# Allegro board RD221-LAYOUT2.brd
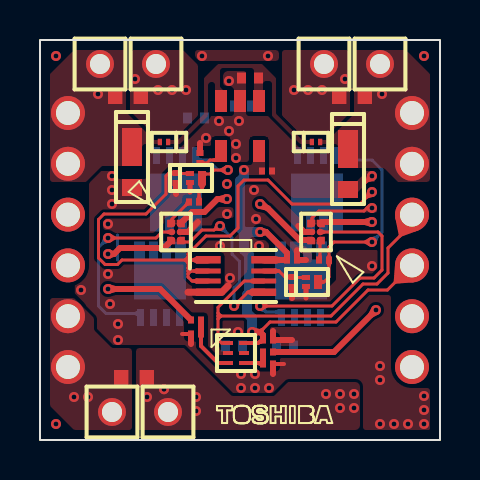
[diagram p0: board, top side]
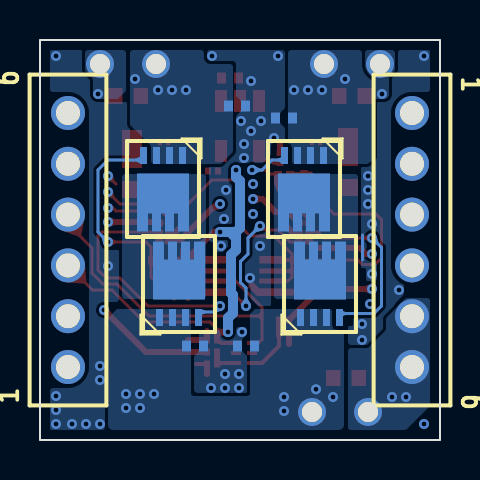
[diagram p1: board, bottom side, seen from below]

Outline 20 x 20 mm; copper layers: TOP, CONDUCTIVE2, CONDUCTIVE3, BOTTOM. Coordinates in mm from the lower left corner of the outline.
Outline path: rectangle 0,0 20,20

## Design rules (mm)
constraint set DEFAULT: 

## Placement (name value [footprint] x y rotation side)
C201  -  [KC00051KD]  10.5 18.1 180 top
C202  -  [KC00540KD]  8 14.1 90 top
C203  -  [KC00540KD]  11.35 13.45 0 top
C204  -  [KC00051KD]  7.8 16.1 0 bottom
C205  -  [KC00051KD]  9.7 4.7 0 bottom
C206  -  [KC00540KD]  11.4 5 0 top
C207  -  [KC00051KD]  10.15 16.7 180 bottom
C208  -  [KC00051KD]  12.25 4.7 180 bottom
C209  -  [KC00540KD]  12.6 9 0 top
CN201  -  [CU12000TD]  1.4 16.35 270 bottom
CN202  -  [CU12000TD]  18.6 3.65 90 bottom
D201  -  [MM02020KD]  4.6 13.9 90 top
D202  -  [MM02020KD]  15.4 13.8 90 top
D203  -  [KC10480CD]  6.2 14.9 0 top
D204  -  [KC10480CD]  13.8 14.9 180 top
DP201  -  [DP002X0KD]  3 18.8 0 top
DP202  -  [DP002X0KD]  5.8 18.8 0 top
DP203  -  [DP002X0KD]  17 18.8 0 top
DP204  -  [DP002X0KD]  14.2 18.8 0 top
DP205  -  [DP002X0KD]  6.4 1.4 0 top
DP206  -  [DP002X0KD]  3.6 1.4 0 top
IC201  -  [MM00631KD]  10 15.7 180 top
IC202  -  [DIC8T60KD]  9.8 8.2 270 top
IC203  -  [LA10251KD]  9.8 4.35 270 top
IC204  -  [BA10620KD]  6.8 10.4 270 top
IC205  -  [BA10620KD]  13.8 10.4 90 top
JP201  -  [KC00081KD]  4.4 17.2 0 top
JP202  -  [KC00081KD]  15.6 17.2 180 top
JP203  -  [KC00081KD]  4.7 3.1 180 top
NOREF  -  []  8 0 0 top
Q201  -  [LA10710KD]  7.8 13.1 0 top
Q202  -  [LA10710KD]  13.6 7.9 0 top
Q203  -  [SN00611KD]  6.8 12.55 0 bottom
Q204  -  [SN00611KD]  6 7.8 180 bottom
Q205  -  [SN00611KD]  13.85 12.55 0 bottom
Q206  -  [SN00611KD]  13.05 7.8 180 bottom
R201  -  [KC00540KD]  7.8 6 0 top
R202  -  [KC00540KD]  7.8 5.3 180 top
R203  -  [KC00540KD]  11.4 4.4 180 top
R204  -  [KC00540KD]  11.4 3.8 0 top
R205  -  [KC00540KD]  7.7 11.9 180 top
R206  -  [KC00540KD]  14.2 9 180 top
R207  -  [KC00540KD]  6.8 13.1 270 top
R208  -  [KC00540KD]  12.6 7.9 270 top

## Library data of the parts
C201 C204 C205 C207 C208 = DP0000016125
C202 = DP0010383000
C203 = DP0007093000
C206 C209 = DP0000015403
CN201 CN202 = DP0010563000
D201 = DP0010580000
D202 = DP0010558000
D203 D204 = DP0010560000
DP201-DP206 = DP9000817000
IC201 = DP0008120000
IC202 = DP0001429000
IC203 = DP0010561000
IC204 = DP0010579000
IC205 = DP0010556000
JP201-JP203 = DP0001376000
Q201 Q202 = DP0010513000
Q203-Q206 = DP0010582000
R201 = DP0000151160
R202 = DP0000151148
R203 R204 = DP0000152120
R205 R206 = DP0000155124
R207 R208 = DP0002867000

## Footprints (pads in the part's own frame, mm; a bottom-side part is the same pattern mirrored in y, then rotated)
BA10620KD
  round 0.325 smd: A1(-0.4,-0.2) A2(-0.4,0.2) B1(0,-0.2) B2(0,0.2) C1(0.4,-0.2) C2(0.4,0.2)
CU12000TD
  round 1.7 hole 1.2: 1(0,0) 2(2.54,0) 3(5.08,0) 4(7.62,0) 5(10.16,0) 6(12.7,0)
DIC8T60KD
  rect 0.375x1.24 smd: 1(-0.812,-1.385) 4(0.812,-1.385) 5(0.812,1.385) 8(-0.812,1.385)
  rect 0.25x1.24 smd: 2(-0.25,-1.385) 3(0.25,-1.385) 6(0.25,1.385) 7(-0.25,1.385)
DP002X0KD
  round 1.397 hole 1: 1(0,0)
KC00051KD
  rect 0.45x0.55 smd: 1(-0.425,0) 2(0.425,0)
KC00081KD
  rect 0.72x0.8 smd: 1(-0.64,0) 2(0.64,0)
KC00540KD
  rect 0.3x0.35 smd: 1(-0.25,0) 2(0.25,0)
KC10480CD
  rect 0.21x0.32 smd: A(-0.205,0) C(0.205,0)
LA10251KD
  rect 0.2x0.5 smd: 1(-0.5,-0.4) 2(0,-0.4) 3(0.5,-0.4) 4(0.5,0.4) 5(0,0.4) 6(-0.5,0.4)
LA10710KD
  rect 0.4x0.7 smd: D(0.3,0)
  rect 0.4x0.25 smd: G(-0.3,0.225) S(-0.3,-0.225)
MM00631KD
  rect 0.6x1.1 smd: 1(-0.95,-1.25) 2(0,-1.25) 3(0.95,-1.25) 4(0.95,1.25) 5(-0.95,1.25)
MM02020KD
  rect 0.85x1 smd: A(-1.275,0)
  rect 1.9x1 smd: C(0.75,0)
SN00611KD
  rect 0.35x0.85 smd: 1(-0.975,-1.675) 2(-0.325,-1.675) 3(0.325,-1.675) 4(0.975,-1.675)
  custom 0.65x0.65 smd: 5(0,0.675)

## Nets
GND: C201.2 C202.2 C203.2 C204.2 C205.2 C206.2 C207.2 C208.2 C209.2 CN201.3 CN201.4 D201.A D202.A IC201.2 IC202.4 IC203.2 IC204.B2 IC205.B2 Q201.S Q202.S R202.2 R204.2 R207.2 R208.2
VINA: CN201.1 CN201.2 D201.C D203.A DP201.1 JP201.1 R201.1
VINB: CN202.5 CN202.6 D202.C D204.A DP203.1 JP202.1 R203.1
EN20V: CN202.1 IC202.1 IC202.2 IC202.3 Q201.G R207.1
FLAG: CN202.4 IC202.6 IC203.1
LDO-VOUT: C203.1 C206.1 C209.1 CN202.3 IC201.5 IC202.8 IC203.6
SIG190: IC204.A1 R205.2
SIG191: IC205.B1 Q206.4
SIG192: IC205.A1 R206.2
SIG193: C207.1 DP204.1 IC205.A2 JP202.2 Q205.1 Q205.2 Q205.3
SIG195: C201.1 D203.C D204.C IC201.1 IC201.3
SIG196: IC203.4 R203.2 R204.1
SIG203: C205.1 C208.1 DP205.1 IC204.C1 IC205.C1 JP203.1 Q204.1 Q204.2 Q204.3 Q206.1 Q206.2 Q206.3
SIG204: IC202.7 Q202.G R208.1
SIG205: C204.1 DP202.1 IC204.A2 JP201.2 Q203.1 Q203.2 Q203.3
SIG206: Q201.D Q203.4 R205.1
SIG207: Q203.5 Q204.5
SIG208: IC204.B1 Q204.4
SIG209: IC202.5 IC204.C2
SIG210: Q205.5 Q206.5
SIG211: Q202.D Q205.4 R206.1
SIG213: IC203.3 R201.2 R202.1
SIG214: C202.1 IC201.4
VCT5V: CN202.2 IC205.C2
VOUT: CN201.5 CN201.6 DP206.1 JP203.2

Pads without a net: IC203 5

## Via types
v1: diameter 0.5, hole 0.25, TOP to BOTTOM, 82 vias

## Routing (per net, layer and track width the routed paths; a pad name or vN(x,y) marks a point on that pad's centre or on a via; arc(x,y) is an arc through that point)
GND: length 21.4
  TOP w0.15: v1(16.6,13.2) 16.2,12.8
  TOP w0.2: 12.2,3.8 R204.2 ; R202.2 7.1,5.3
  TOP w0.25: Q202.S 13.3,7.1 ; Q201.S 7.5,12.4
  TOP w0.3: 12.85,9.49 C209.2 13.3,9 ; R202.2 7.55,4.8 ; R207.2 6.8,12.3 ; R208.2 12.6,7.1 ; IC205.B2 13.22,10.4 12.92,10.7 ; 12.6,5 C206.2 11.65,5.45 ; R204.2 11.65,3.3 ; IC204.B2 7.4,10.4 7.9,10.9 ; C202.2 8,14.85
  TOP w0.35: 7.4,7.39 IC202.4 9.09,7.39 9.41,7.71
  CONDUCTIVE2 w0.15: 6.15,0.57 6.67,0.57 ; 3.35,0.57 3.9,0.57
  CONDUCTIVE2 w1: 1.4,12.45 CN201.3 ; CN201.3 CN201.4 ; CN201.3 2.5,11.27 ; CN201.4 1.4,7.55 ; CN201.4 2.4,8.73
  CONDUCTIVE3 w0.15: 6.17,0.57 6.62,0.57
  BOTTOM w0.15: 3.88,10.25 3.88,9
  vias: v1(0.8,19.2) v1(0.8,0.8) v1(2.05,7.5) v1(3.4,10.8) v1(3.4,8.3) v1(3.5,6.8) v1(3.6,13.2) v1(3.6,12.5) v1(3.6,11.8) v1(3.9,5.8) v1(3.9,5) v1(8.1,19.2) v1(8.3,15.1) v1(8.95,15.95) v1(9,9.7) v1(9.35,12.8) v1(9.35,11.3) v1(9.45,17.95) v1(9.45,15.45) v1(9.5,8.1) v1(9.8,14.8) v1(9.8,14.1) v1(9.95,15.95) v1(9.9,5.4) v1(10.05,3.3) v1(10.05,2.6) v1(10.7,12.5) v1(10.8,11.05) v1(10.75,3.3) v1(10.75,2.6) v1(10.95,9.7) v1(11.4,19.2) v1(11.45,2.6) v1(16.6,8.7) v1(17,3.7) v1(17,3) v1(17,0.8) v1(17.7,0.8) v1(18.4,0.8) v1(19.2,19.2) v1(19.2,2.2) v1(19.2,1.5) v1(19.2,0.8)
VINA: length 15.2
  TOP w0.3: v1(3.4,7.55) 6,7.55 R201.1
  CONDUCTIVE3 w0.6: v1(3.4,7.55) 3.05,7.55 2.65,7.95 2.65,17.05 v1(2.9,17.3)
VINB: length 17.2
  TOP w0.3: v1(16.8,6.5) 14.7,4.4 R203.1
  CONDUCTIVE3 w0.6: v1(17.1,17.3) 17.35,16.79 17.35,6.85 17,6.5 v1(16.8,6.5)
EN20V: length 41.1
  TOP w0.15: 7.4,8.85 7.4,9 ; 7.4,8.85 7.25,9 ; 7.4,8.85 7.4,8.6 ; 7.4,8.85 7.55,9 ; 7.4,9 7.25,9 ; 7.4,9 7.55,9 ; 7.4,9 7.4,9.15 ; 7.4,8.45 7.4,8.6 ; 7.4,8.45 7.4,8.3 ; 7.4,8.45 7.55,8.45 ; 7.4,8.6 7.55,8.45 ; 7.25,9 7.4,9.15 ; 7.25,9 4.1,9 3.88,8.78 3.25,8.78 2.92,9.1 2.92,11.03 3.2,11.3 5.3,11.3 6.3,12.3 6.3,13.2 6.45,13.35 R207.1 7.1,13.32 7.42,13.32 ; 7.4,9.15 7.4,9.3 8.3,10.2 9.5,10.2 9.9,10.6 9.9,12.7 10.2,13 11.4,13 12.6,11.8 16,11.8 v1(16.6,12.4) ; 7.4,9.15 7.55,9 ; 7.55,8.45 7.83,8.45 ; 7.55,8.45 7.4,8.3 ; 7.55,9 7.87,9 ; 7.4,8.3 7.4,8.15 7.6,7.95 7.83,7.95
  TOP w0.25: IC202.3 7.83,7.95 ; Q201.G 7.42,13.32 ; 7.83,8.45 IC202.2
  TOP w0.35: 7.87,9 8.4,9
  CONDUCTIVE2 w0.15: v1(16.6,12.4) 16.05,11.85 16.05,10.8 16.5,10.35 16.8,10.35 17.25,9.9 17.25,5 CN202.1
FLAG: length 18.2
  TOP w0.15: CN202.4 18,10.2 17.4,9.6 17.4,8.35 16.85,7.8 16.15,7.8 14.55,6.2 9.05,6.2 ; 8.9,6.2 8.9,6.35 ; 8.9,6.2 8.9,6.05 ; 8.9,6.2 9.05,6.2 ; 8.9,6.35 9.05,6.2 ; 8.9,6.35 8.9,6.63 10.22,7.95 10.69,7.95 ; 9.05,6.2 8.9,6.05 ; 9.25,4.85 9.07,4.85 8.9,5.03 8.9,6.05
  TOP w0.2: 9.25,4.85 IC203.1
  TOP w0.25: IC202.6 10.69,7.95
LDO-VOUT: length 23.9
  TOP w0.15: CN202.3 17.37,7.5 16.4,7.5 14.8,5.9 11.5,5.9 11,5.4
  TOP w0.2: C206.1 10.9,4.85 IC203.6
  TOP w0.3: v1(10.6,5.4) 11,5.4 11.15,5.25 C206.1 ; 11.79,9 C209.1 12.35,9.36 11.31,10.4 v1(11,10.4)
  TOP w0.35: 11.79,9 11.19,9
  BOTTOM w0.5: 10.2,10.1 10.2,10.4 ; 10.2,10.1 10.2,9.5 10.45,9.25 10.45,7.35 10.35,7.25 10.35,6.35 10.6,6.1 v1(10.6,5.4) ; 10.2,10.1 10.5,10.4 ; 10.2,10.4 10,10.6 10,12.95 10.2,13.15 v1(10.2,13.5) ; 10.2,10.4 10.5,10.4 ; 10.5,10.4 v1(11,10.4)
SIG190: length 1.5
  TOP w0.15: IC204.A1 6.6,11.05 R205.2
SIG191: length 12.9
  TOP w0.15: v1(11,6.7) 14.6,6.7 16,8.1 16.7,8.1 17.1,8.5 17.1,10.2 16.9,10.4 IC205.B1
  BOTTOM w0.15: 11.98,6.4 11.3,6.4 v1(11,6.7)
  BOTTOM w0.3: 11.98,6.4 12.07,6.4
SIG192: length 1
  TOP w0.15: R206.2 14,9.2 IC205.A1
SIG193: length 9.9
  TOP w0.3: v1(11,11.8) 11.4,11.58 12.98,10 IC205.A2
  CONDUCTIVE3 w0.6: v1(12.7,17.5) 11.9,16.7 11.9,12.4 11.3,11.8 v1(11,11.8)
  vias: v1(13.4,17.5) v1(14.1,17.5) v1(15.25,18.05)
SIG196: length 1.6
  TOP w0.2: R204.1 10.9,3.85 IC203.4
  TOP w0.3: R203.2 R204.1
SIG203: length 28.1
  TOP w0.3: v1(3.4,9.3) 3.7,9.3 4,9.6 6.2,9.6 IC204.C1 ; IC205.C1 14.1,10.9 v1(16.6,10.9)
  CONDUCTIVE3 w0.5: v1(3.4,9.3) 5.15,9.3 5.35,9.1 ; 5.35,9.1 5.35,8.35 ; 5.35,9.1 5.55,8.9 5.9,8.9 ; 5.35,8.35 v1(5.35,2.15) ; 5.35,8.35 5.9,8.9 ; 5.9,8.9 11.3,8.9 13.3,10.9 v1(16.6,10.9)
  vias: v1(6.2,2.54) v1(7.8,2.15) v1(7.8,1.45) v1(14.3,2.3) v1(15,2.3) v1(15,1.6) v1(15.7,2.3) v1(15.7,1.6)
SIG204: length 2.2
  TOP w0.15: 13.22,8.12 12.9,8.12 R208.1 12.25,8.15 11.95,8.45 11.77,8.45
  TOP w0.25: Q202.G 13.22,8.12 ; 11.77,8.45 IC202.7
SIG205: length 9.6
  TOP w0.3: v1(9.35,12.05) 8.87,12.05 8.22,11.4 7.6,11.4 IC204.A2
  CONDUCTIVE3 w0.6: v1(7.3,17.5) 7.3,13.4 8.65,12.05 v1(9.35,12.05)
  vias: v1(4.75,18.05) v1(5.9,17.5) v1(6.6,17.5)
SIG206: length 4.5
  TOP w0.15: 8.1,12.84 8.1,12.5 7.95,12.35 7.95,11.99 ; 8.1,13.3 8.5,13.3 8.7,13.5 v1(9.4,13.5)
  TOP w0.3: R205.1 7.95,11.99
  TOP w0.4: 8.1,12.84 Q201.D
  BOTTOM w0.15: 7.87,14 8.4,14 8.9,13.5 v1(9.4,13.5)
  BOTTOM w0.3: 7.87,14 7.78,14
SIG208: length 9.2
  TOP w0.15: v1(3.4,10.1) 5.8,10.1 6.1,10.4 IC204.B1
  BOTTOM w0.15: 4.95,6.33 3.3,6.33 2.92,6.7 2.92,9.62 v1(3.4,10.1)
  BOTTOM w0.3: 5.05,6.33 4.95,6.33
SIG209: length 8.6
  TOP w0.15: v1(9,10.7) 8.7,10.5 8.1,10.5 7.5,9.9 7.25,9.9 IC204.C2 ; v1(9.7,6.7) 10.39,7.39 10.65,7.39
  TOP w0.37: 10.65,7.39 IC202.5
  BOTTOM w0.15: v1(9,10.7) 9.6,10.1 9.6,9.3 9.97,8.93 9.97,7.88 9.7,7.6 v1(9.7,6.7)
SIG211: length 10.7
  TOP w0.15: 14.45,8.9 14.45,8.15 14.2,7.9 Q202.D ; v1(16.6,9.9) 14.7,9.9 14.45,9.65 14.45,9.02
  TOP w0.3: 14.45,8.9 R206.1 14.45,9.02
  BOTTOM w0.15: v1(16.6,9.9) 17.1,10.4 17.1,13.5 16.6,14 14.93,14
  BOTTOM w0.35: 14.82,14 14.93,14
SIG213: length 3
  TOP w0.2: IC203.3 8.9,3.85 8.05,4.7 R202.1
  TOP w0.3: R202.1 R201.2
SIG214: length 1.1
  TOP w0.15: 8.02,13.85 8.35,13.85 8.5,14 8.77,14
  TOP w0.2: 8.77,14 9,14
  TOP w0.3: C202.1 8.02,13.85
VCT5V: length 9.7
  TOP w0.15: IC205.C2 13.6,11.1 13.95,11.45 16.2,11.45 16.35,11.6 v1(16.6,11.6)
  CONDUCTIVE2 w0.15: CN202.2 17.65,7.14 17.65,10.55 v1(16.6,11.6)
VOUT:
  vias: v1(1.7,2.15) v1(2.4,2.15)

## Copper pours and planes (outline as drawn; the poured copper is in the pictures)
GND on TOP: 9.28,5.15 9.17,5.19 9.12,5.3 9.12,5.9 9.15,5.95 9.2,5.97 10.12,5.97 10.18,5.95 10.2,5.9 10.2,5.3 10.16,5.19 10.05,5.15
GND on TOP: 3.79,10.35 3.77,10.35 3.75,10.36 3.5,10.49 3.4,10.5 3.3,10.5 3.19,10.54 3.15,10.65 3.15,10.9 3.16,10.93 3.17,10.95 3.27,11.05 3.3,11.07 3.32,11.07 5.3,11.07 5.39,11.09 5.46,11.14 6.46,12.14 6.52,12.24 6.53,12.3 6.53,12.35 6.57,12.46 6.67,12.5 7.55,12.5 7.6,12.48 7.62,12.43 7.62,12.35 7.6,12.3 7.55,12.28 7.33,12.28 7.17,12.21 7.1,12.05 7.1,11.9 7.09,11.87 7.08,11.85 6.44,11.21 6.4,11.17 6.38,11.16 6.26,11.08 6.21,10.94 6.21,10.91 6.2,10.89 6.19,10.86 5.7,10.37 5.67,10.36 5.64,10.35
GND on TOP: 8.02,18.95 7.92,18.99 7.79,19.12 7.75,19.22 7.75,19.35 7.79,19.46 7.9,19.5 11.8,19.5 11.91,19.46 11.95,19.35 11.95,19.1 11.91,18.99 11.8,18.95
GND on TOP: outline of 88 points within 7.93,7.4 13.6,12.78
GND on TOP: 12.53,6.92 12.47,6.95 12.45,7 12.45,7.22 12.47,7.28 12.53,7.3 14.04,7.3 14.1,7.31 14.14,7.34 14.76,7.96 14.79,8 14.8,8.06 14.8,9.27 14.81,9.3 14.82,9.32 14.98,9.48 15,9.49 15.03,9.5 16.8,9.5 16.85,9.48 16.88,9.43 16.88,8.62 16.87,8.6 16.85,8.57 16.63,8.35 16.6,8.33 16.58,8.32 16,8.32 15.91,8.31 15.84,8.26 14.53,6.95 14.5,6.93 14.48,6.92
GND on TOP: outline of 298 points within 1.74,0.5 19.5,18.45
GND on BOTTOM: outline of 105 points within 0.5,4.75 4.6,19.5
GND on BOTTOM: 16.9,0.5 16.79,0.54 16.75,0.65 16.75,6.03 16.77,6.08 16.82,6.1 17.2,6.51 16.8,6.9 16.2,6.9 16.09,6.94 16.05,7.05 16.05,9.43 16.07,9.48 16.12,9.5 16.6,9.5 16.84,9.58 16.99,9.79 17.04,10.01 17.06,10.05 17.26,10.24 17.31,10.31 17.32,10.4 17.32,13.5 17.31,13.59 17.26,13.66 16.76,14.16 16.69,14.21 16.6,14.22 15.57,14.22 15.52,14.25 15.5,14.3 15.5,15.51 15.51,15.54 15.52,15.56 15.56,15.6 15.63,15.7 15.65,15.81 15.65,16.82 15.67,16.88 15.72,16.9 17.1,16.9 17.38,17.02 17.5,17.3 17.5,17.96 17.51,17.99 17.52,18.01 17.81,18.3 17.86,18.35 17.88,18.42 17.9,18.46 17.9,18.51 17.9,19.35 17.89,19.41 17.91,19.47 17.97,19.5 19.43,19.5 19.48,19.48 19.5,19.43 19.5,17.55 19.46,17.44 19.35,17.4 18.6,17.4 17.86,17.09 17.55,16.35 17.55,3.65 17.86,2.91 18.6,2.6 19.35,2.6 19.46,2.56 19.5,2.45 19.5,0.57 19.48,0.52 19.43,0.5
GND on BOTTOM: outline of 95 points within 7.75,9.4 11.65,19.5 ; 1 cut-out
GND on CONDUCTIVE2: outline of 155 points within 0.5,0.5 19.5,19.5 ; 22 cut-outs
GND on CONDUCTIVE3: outline of 101 points within 0.5,9.3 19.5,19.5 ; 7 cut-outs
GND on CONDUCTIVE3: outline of 115 points within 0.5,0.5 19.5,10.5 ; 6 cut-outs
VINA on BOTTOM: 2.8,17.05 2.62,17.12 2.55,17.3 2.55,18.09 2.51,18.19 2.29,18.41 2.25,18.51 2.25,19.35 2.29,19.46 2.4,19.5 3.6,19.5 3.7,19.47 3.75,19.38 3.75,19.35 3.75,18.8 3.67,18.46 3.44,18.2 3.34,18.12 3.27,18.04 3.25,17.94 3.25,17.12 3.23,17.07 3.17,17.05
VINB on TOP: 17.92,12.9 17.88,12.91 17.86,12.94 17.24,13.56 17.14,13.6 15.05,13.6 14.94,13.64 14.9,13.75 14.9,14.65 14.86,14.76 14.75,14.8 13.97,14.8 13.92,14.82 13.9,14.88 13.9,14.93 13.92,14.98 13.97,15 14.28,15 14.39,15.02 14.49,15.09 15.66,16.26 15.69,16.3 15.7,16.36 15.7,19.35 15.74,19.46 15.85,19.5 18.24,19.5 18.3,19.49 18.34,19.46 19.46,18.34 19.49,18.3 19.5,18.24 19.5,13.05 19.46,12.94 19.35,12.9
VINB on BOTTOM: 16.16,17.05 16.06,17.09 15.74,17.41 15.7,17.51 15.7,19.35 15.74,19.46 15.85,19.5 17.6,19.5 17.71,19.46 17.75,19.35 17.75,18.51 17.71,18.41 17.39,18.09 17.35,17.99 17.35,17.3 17.32,17.18 17.23,17.08 17.1,17.05
LDO-VOUT on TOP: 10.1,13.25 9.99,13.29 9.95,13.4 9.95,13.6 9.99,13.71 10.1,13.75 10.49,13.75 10.55,13.76 10.59,13.79 10.61,13.81 10.65,13.91 10.65,14.75 10.69,14.86 10.8,14.9 11.1,14.9 11.21,14.86 11.25,14.75 11.25,13.4 11.21,13.29 11.1,13.25
SIG193 on TOP: 13.01,15.35 12.98,15.36 12.95,15.37 12.12,16.2 12.11,16.23 12.1,16.26 12.1,19.35 12.14,19.46 12.25,19.5 15.35,19.5 15.46,19.46 15.5,19.35 15.5,16.41 15.46,16.31 14.54,15.39 14.44,15.35
SIG193 on BOTTOM: 11.01,13.8 10.95,13.81 10.91,13.84 10.39,14.36 10.35,14.46 10.35,18.65 10.39,18.76 10.5,18.8 11.54,18.8 11.64,18.84 11.76,18.96 11.8,19.06 11.8,19.35 11.84,19.46 11.95,19.5 15.35,19.5 15.46,19.46 15.5,19.35 15.5,15.81 15.49,15.75 15.46,15.71 14.49,14.74 14.46,14.7 14.45,14.64 14.45,13.93 14.43,13.87 14.38,13.85 14.35,13.81 14.3,13.8
SIG195 on TOP: outline of 82 points within 6.3,14.8 13.7,18.8
SIG203 on TOP: 5.05,0.5 4.92,0.53 4.83,0.62 4.8,0.75 4.8,4.45 4.84,4.56 4.95,4.6 7.16,4.6 7.19,4.59 7.21,4.58 9.54,2.24 9.65,2.2 11.64,2.2 11.7,2.21 11.74,2.24 12.36,2.86 12.4,2.89 12.46,2.9 15.75,2.9 15.93,2.83 16,2.65 16,0.75 15.93,0.57 15.75,0.5
SIG203 on BOTTOM: 5.05,0.5 4.92,0.53 4.83,0.62 4.8,0.75 4.8,5.35 4.84,5.46 4.95,5.5 5.12,5.5 5.26,5.54 5.36,5.64 5.4,5.78 5.4,6.4 5.44,6.51 5.55,6.55 9.19,6.55 9.25,6.54 9.29,6.51 9.46,6.34 9.49,6.3 9.5,6.24 9.5,2.35 9.54,2.24 9.65,2.2 12.3,2.2 12.41,2.24 12.45,2.35 12.45,6.47 12.47,6.53 12.53,6.55 16.09,6.55 16.15,6.54 16.19,6.51 16.56,6.14 16.59,6.1 16.6,6.04 16.6,0.75 16.57,0.62 16.48,0.53 16.35,0.5
SIG203 on CONDUCTIVE3: 7.65,1 7.54,1.04 7.5,1.15 7.5,2.3 7.54,2.41 7.65,2.45 9.39,2.45 9.45,2.44 9.49,2.41 9.76,2.14 9.86,2.1 11.74,2.1 11.84,2.14 12.26,2.56 12.36,2.6 15.85,2.6 15.96,2.56 16,2.45 16,1.15 15.96,1.04 15.85,1
SIG205 on TOP: 4.54,16.41 4.51,16.45 4.5,16.51 4.5,19.35 4.54,19.46 4.65,19.5 7.09,19.5 7.19,19.46 7.86,18.79 7.9,18.69 7.9,16.26 7.89,16.23 7.88,16.2 7.05,15.37 7.02,15.36 6.99,15.35 5.66,15.35 5.6,15.36 5.56,15.39
SIG205 on BOTTOM: 3.66,13.8 3.6,13.81 3.56,13.84 3.34,14.06 3.31,14.1 3.3,14.16 3.3,16.84 3.31,16.9 3.34,16.94 3.36,16.96 3.39,17 3.4,17.06 3.4,17.94 3.41,17.98 3.43,18 3.8,18.39 3.9,18.8 3.9,19.35 3.94,19.46 4.05,19.5 7.45,19.5 7.56,19.46 7.6,19.35 7.6,14.89 7.59,14.85 7.44,14.72 7.4,14.57 7.4,13.95 7.36,13.84 7.25,13.8
SIG207 on BOTTOM: 4.25,7.05 4.14,7.09 4.1,7.2 4.1,13.15 4.14,13.26 4.25,13.3 8.15,13.3 8.26,13.26 8.3,13.15 8.3,7.2 8.26,7.09 8.15,7.05
SIG210 on BOTTOM: 11.85,7.05 11.74,7.09 11.7,7.2 11.7,13.15 11.74,13.26 11.85,13.3 15.75,13.3 15.86,13.26 15.9,13.15 15.9,7.2 15.86,7.09 15.75,7.05
VOUT on TOP: 1.8,0.5 1.71,0.52 1.63,0.57 0.57,1.63 0.52,1.71 0.5,1.8 0.5,6.95 0.54,7.06 0.65,7.1 1.6,7.1 1.69,7.08 1.77,7.03 2.66,6.14 2.7,6.04 2.7,5.56 2.74,5.46 3.56,4.64 3.66,4.6 4.45,4.6 4.56,4.56 4.6,4.45 4.6,0.65 4.56,0.54 4.45,0.5
VOUT on BOTTOM: 1.8,0.5 1.71,0.52 1.63,0.57 0.57,1.63 0.52,1.71 0.5,1.8 0.5,6.95 0.54,7.06 0.65,7.1 1.64,7.1 1.7,7.09 1.74,7.06 2.66,6.14 2.7,6.04 2.7,5.56 2.74,5.46 3.56,4.64 3.66,4.6 4.45,4.6 4.56,4.56 4.6,4.45 4.6,0.65 4.56,0.54 4.45,0.5

Small or netless copper shapes (teardrops, artwork), in the pictures only: 64 on TOP, 12 on BOTTOM, 4 on CONDUCTIVE2, 3 on CONDUCTIVE3

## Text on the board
Ref Des/Silkscreen Bottom: 1 | 6
SYMBOL-2-TOP: IC201 | IC202 | IC203 | MUX2 | D201 | IC204 | D202 | IC205 | VINA | VOUT | GND | FLAG | VINB
SYMBOL-2-BOTTOM: 1 | Q203 | Q204 | Q206 | Q205
SYMBOL-1-BOTTOM: 1 | 6
